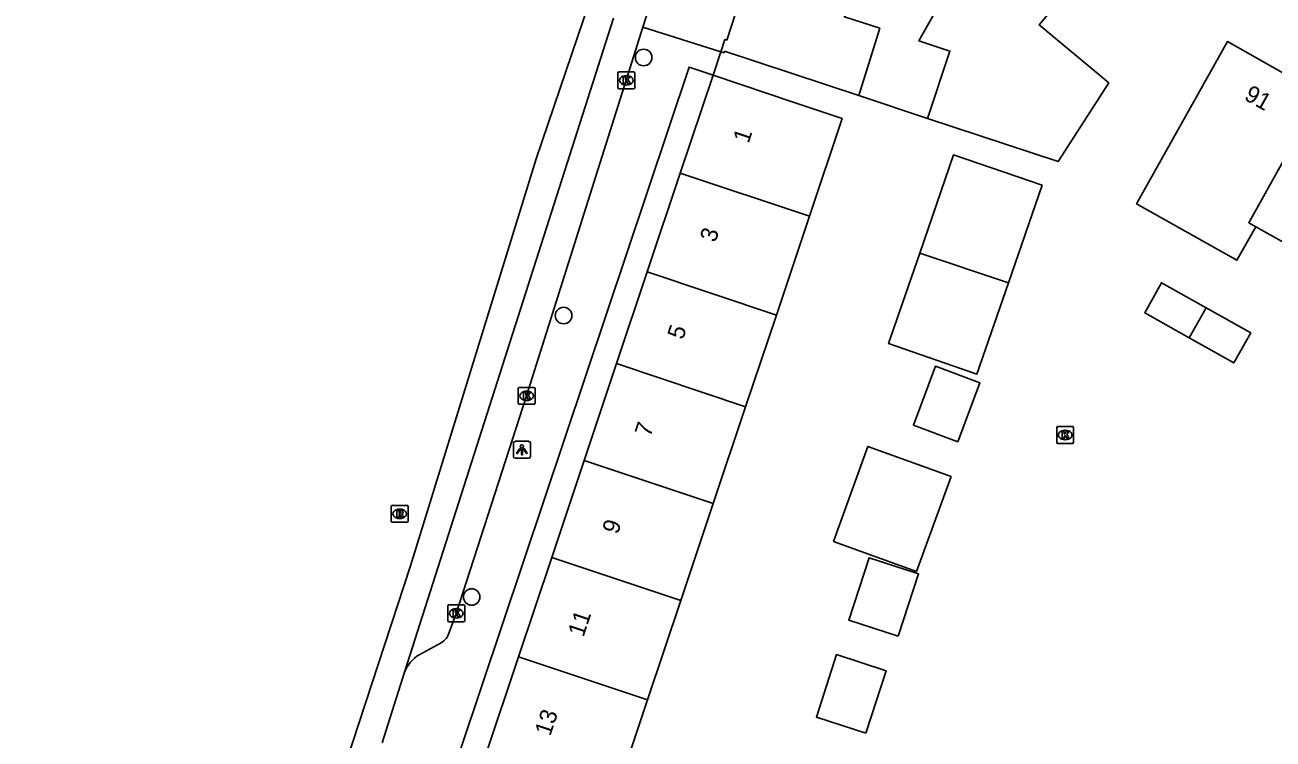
# Model space of a CAD drawing. Extents: x 163150 to 163546, y 380933 to 381635.
# Drawn here: x 163218.8 to 163292.5, y 381558 to 381600.2 of the extents above; entities that cross this region are included whole.
import ezdxf

# ---------------------------------------------------------------- set-up
doc = ezdxf.new("R2010")
doc.units = 0
for name, color, linetype in [('IMGEO_Boom', 7, 'Continuous'), ('IMGEO_Fietspad_gesloten', 7, 'Continuous'), ('IMGEO_Kolk', 7, 'Continuous'), ('IMGEO_Lichtpunt', 7, 'Continuous'), ('IMGEO_Pand', 7, 'Continuous'), ('IMGEO_Pand_nummerreeks', 7, 'Continuous'), ('IMGEO_Rijbaan_lokaal_gesloten', 7, 'Continuous'), ('IMGEO_Rioolput', 7, 'Continuous'), ('IMGEO_Voetpad_open', 7, 'Continuous')]:
    doc.layers.add(name, color=color, linetype=linetype)

msp = doc.modelspace()

# ---------------------------------------------------------------- linework, layer by layer
at = {"layer": 'IMGEO_Boom'}
for centre in [(163255.328, 381598.265), (163250.601, 381583.028), (163245.175, 381566.408)]:
    msp.add_circle(centre, 0.489, dxfattribs=at)
at = {"layer": 'IMGEO_Fietspad_gesloten'}
for points in [[(163253.553, 381600.588), (163241.214, 381561.974)], [(163241.214, 381561.974), (163239.892, 381557.795)]]:
    msp.add_lwpolyline(points, dxfattribs=at)
at = {"layer": 'IMGEO_Kolk'}
for p, q in [((163253.809, 381596.493), (163253.809, 381597.345)), ((163253.884, 381597.419), (163254.736, 381597.419)), ((163254.297, 381597.199), (163254.322, 381597.199)), ((163254.81, 381597.345), (163254.81, 381596.493)), ((163254.736, 381596.419), (163253.884, 381596.419)), ((163254.32, 381596.639), (163254.295, 381596.639)), ((163247.92, 381577.859), (163247.92, 381578.711)), ((163247.995, 381578.785), (163248.847, 381578.785)), ((163248.408, 381578.565), (163248.433, 381578.565)), ((163248.921, 381578.711), (163248.921, 381577.859)), ((163248.847, 381577.785), (163247.995, 381577.785)), ((163248.431, 381578.005), (163248.406, 381578.005)), ((163279.718, 381575.55), (163279.718, 381576.402)), ((163279.793, 381576.476), (163280.645, 381576.476)), ((163280.206, 381576.256), (163280.231, 381576.256)), ((163280.719, 381576.402), (163280.719, 381575.55)), ((163280.229, 381575.696), (163280.204, 381575.696)), ((163280.645, 381575.476), (163279.793, 381575.476)), ((163243.843, 381565.94), (163244.695, 381565.94)), ((163243.768, 381565.014), (163243.768, 381565.866)), ((163244.256, 381565.72), (163244.281, 381565.72)), ((163244.769, 381565.866), (163244.769, 381565.014)), ((163244.695, 381564.94), (163243.843, 381564.94)), ((163244.279, 381565.16), (163244.254, 381565.16))]:
    msp.add_line(p, q, dxfattribs=at)
for points in [[(163253.809, 381596.493), (163253.809, 381597.345)], [(163253.884, 381597.419), (163254.736, 381597.419)], [(163254.13, 381597.119), (163254.253, 381597.119), (163254.253, 381596.968), (163254.383, 381597.119), (163254.547, 381597.119), (163254.401, 381596.968), (163254.554, 381596.719), (163254.402, 381596.719), (163254.317, 381596.883), (163254.253, 381596.816), (163254.253, 381596.719), (163254.13, 381596.719), (163254.13, 381597.119)], [(163254.81, 381597.345), (163254.81, 381596.493)], [(163254.736, 381596.419), (163253.884, 381596.419)], [(163247.92, 381577.859), (163247.92, 381578.711)], [(163247.995, 381578.785), (163248.847, 381578.785)], [(163248.241, 381578.485), (163248.364, 381578.485), (163248.364, 381578.334), (163248.494, 381578.485), (163248.658, 381578.485), (163248.512, 381578.334), (163248.665, 381578.085), (163248.513, 381578.085), (163248.428, 381578.249), (163248.364, 381578.182), (163248.364, 381578.085), (163248.241, 381578.085), (163248.241, 381578.485)], [(163248.921, 381578.711), (163248.921, 381577.859)], [(163248.847, 381577.785), (163247.995, 381577.785)], [(163279.718, 381575.55), (163279.718, 381576.402)], [(163279.793, 381576.476), (163280.645, 381576.476)], [(163280.719, 381576.402), (163280.719, 381575.55)], [(163280.039, 381576.176), (163280.162, 381576.176), (163280.162, 381576.025), (163280.292, 381576.176), (163280.456, 381576.176), (163280.31, 381576.025), (163280.463, 381575.776), (163280.311, 381575.776), (163280.226, 381575.94), (163280.162, 381575.873), (163280.162, 381575.776), (163280.039, 381575.776), (163280.039, 381576.176)], [(163280.645, 381575.476), (163279.793, 381575.476)], [(163243.843, 381565.94), (163244.695, 381565.94)], [(163243.768, 381565.014), (163243.768, 381565.866)], [(163244.089, 381565.64), (163244.212, 381565.64), (163244.212, 381565.489), (163244.342, 381565.64), (163244.506, 381565.64), (163244.36, 381565.489), (163244.513, 381565.24), (163244.361, 381565.24), (163244.276, 381565.404), (163244.212, 381565.337), (163244.212, 381565.24), (163244.089, 381565.24), (163244.089, 381565.64)], [(163244.769, 381565.866), (163244.769, 381565.014)], [(163244.695, 381564.94), (163243.843, 381564.94)]]:
    msp.add_lwpolyline(points, dxfattribs=at)
for centre, start, end in [((163253.886, 381597.343), 91.55205, 178.44795), ((163253.886, 381597.343), 91.55205, 178.44795), ((163254.734, 381597.343), 1.55205, 88.44795), ((163254.734, 381597.343), 1.55205, 88.44795), ((163253.886, 381596.495), 181.55205, 268.44795), ((163253.886, 381596.495), 181.55205, 268.44795), ((163254.734, 381596.495), 271.55205, 358.44795), ((163254.734, 381596.495), 271.55205, 358.44795), ((163247.997, 381578.709), 91.55205, 178.44795), ((163247.997, 381578.709), 91.55205, 178.44795), ((163248.845, 381578.709), 1.55205, 88.44795), ((163248.845, 381578.709), 1.55205, 88.44795), ((163247.997, 381577.861), 181.55205, 268.44795), ((163247.997, 381577.861), 181.55205, 268.44795), ((163248.845, 381577.861), 271.55205, 358.44795), ((163248.845, 381577.861), 271.55205, 358.44795), ((163279.795, 381576.4), 91.55205, 178.44795), ((163279.795, 381576.4), 91.55205, 178.44795), ((163280.643, 381576.4), 1.55205, 88.44795), ((163280.643, 381576.4), 1.55205, 88.44795), ((163279.795, 381575.552), 181.55205, 268.44795), ((163279.795, 381575.552), 181.55205, 268.44795), ((163280.643, 381575.552), 271.55205, 358.44795), ((163280.643, 381575.552), 271.55205, 358.44795), ((163243.845, 381565.864), 91.55205, 178.44795), ((163243.845, 381565.864), 91.55205, 178.44795), ((163244.693, 381565.864), 1.55205, 88.44795), ((163244.693, 381565.864), 1.55205, 88.44795), ((163243.845, 381565.016), 181.55205, 268.44795), ((163243.845, 381565.016), 181.55205, 268.44795), ((163244.693, 381565.016), 271.55205, 358.44795), ((163244.693, 381565.016), 271.55205, 358.44795)]:
    msp.add_arc(centre, 0.0765, start, end, dxfattribs=at)
for centre, major_axis, ratio, start_param, end_param in [((163254.296, 381596.919), (-0.387, 0.002), 0.722429, 4.712389, 7.853982), ((163254.321, 381596.919), (-0.39, 0.002), 0.717154, 1.570796, 4.712389), ((163248.407, 381578.285), (-0.387, 0.002), 0.722429, 4.712389, 7.853982), ((163248.432, 381578.285), (-0.39, 0.002), 0.717154, 1.570796, 4.712389), ((163280.205, 381575.976), (-0.387, 0.002), 0.722429, 4.712389, 7.853982), ((163280.23, 381575.976), (-0.39, 0.002), 0.717154, 1.570796, 4.712389), ((163244.255, 381565.44), (-0.387, 0.002), 0.722429, 4.712389, 7.853982), ((163244.28, 381565.44), (-0.39, 0.002), 0.717154, 1.570796, 4.712389)]:
    msp.add_ellipse(centre, major_axis=major_axis, ratio=ratio, start_param=start_param, end_param=end_param, dxfattribs=at)
at = {"layer": 'IMGEO_Lichtpunt'}
for p, q in [((163248.546, 381575.6), (163247.738, 381575.6)), ((163248.546, 381575.6), (163247.738, 381575.6)), ((163247.644, 381575.505), (163247.644, 381574.698)), ((163247.644, 381575.505), (163247.644, 381574.698)), ((163248.64, 381574.698), (163248.64, 381575.505)), ((163248.64, 381574.698), (163248.64, 381575.505)), ((163247.738, 381574.604), (163248.546, 381574.604)), ((163247.738, 381574.604), (163248.546, 381574.604))]:
    msp.add_line(p, q, dxfattribs=at)
for points in [[(163248.018, 381575.169), (163248.057, 381575.141), (163247.869, 381574.879), (163247.831, 381574.906), (163248.018, 381575.169)], [(163248.12, 381575.121), (163248.167, 381575.121), (163248.167, 381574.799), (163248.12, 381574.799), (163248.12, 381575.121)], [(163248.23, 381575.141), (163248.268, 381575.168), (163248.455, 381574.906), (163248.416, 381574.878), (163248.23, 381575.141)]]:
    msp.add_lwpolyline(points, dxfattribs=at)
msp.add_circle((163248.143, 381575.303), 0.0994, dxfattribs=at)
for centre, start, end in [((163247.738, 381575.505), 90, 180), ((163247.738, 381575.505), 90, 180), ((163248.546, 381575.505), 0, 90), ((163248.546, 381575.505), 0, 90), ((163247.738, 381574.698), 180, 270), ((163247.738, 381574.698), 180, 270), ((163248.546, 381574.698), 270, 0), ((163248.546, 381574.698), 270, 360)]:
    msp.add_arc(centre, 0.0946, start, end, dxfattribs=at)
at = {"layer": 'IMGEO_Pand'}
for points in [[(163276.149, 381614.464), (163269.4, 381606.423), (163267.187, 381600.676), (163269.266, 381599.996), (163268.035, 381596.014)], [(163280.295, 381610.934), (163273.609, 381602.862), (163271.582, 381599.255), (163273.399, 381598.644), (163272.09, 381594.672)], [(163286.053, 381608.305), (163285.797, 381607.998), (163285.439, 381608.296), (163278.684, 381600.193), (163282.792, 381596.768), (163279.804, 381592.118), (163272.09, 381594.672)], [(163262.321, 381605.753), (163261.296, 381602.58), (163260.232, 381599.291), (163260.129, 381599.328), (163259.878, 381598.61)], [(163291.473, 381588.273), (163290.364, 381586.292), (163284.431, 381589.615), (163289.803, 381599.209), (163295.296, 381596.106)], [(163268.035, 381596.014), (163260.111, 381598.637), (163260.077, 381598.542), (163259.878, 381598.61)], [(163257.492, 381591.438), (163259.425, 381597.215)], [(163259.425, 381597.215), (163264.156, 381595.634), (163267.048, 381594.665), (163265.116, 381588.888)], [(163272.09, 381594.672), (163268.035, 381596.014)], [(163291.473, 381588.273), (163291.059, 381588.505), (163295.296, 381596.106)], [(163271.63, 381586.709), (163273.631, 381592.518), (163278.853, 381590.719), (163276.867, 381584.957)], [(163255.542, 381585.608), (163257.492, 381591.438)], [(163257.492, 381591.438), (163265.116, 381588.888)], [(163265.116, 381588.888), (163263.165, 381583.058)], [(163296.548, 381585.428), (163291.473, 381588.273)], [(163276.867, 381584.957), (163275.012, 381579.573), (163269.79, 381581.372), (163271.63, 381586.709)], [(163276.867, 381584.957), (163271.63, 381586.709)], [(163253.729, 381580.189), (163255.542, 381585.608)], [(163263.165, 381583.058), (163255.542, 381585.608)], [(163287.546, 381581.708), (163284.919, 381583.187), (163285.904, 381584.969), (163288.544, 381583.481)], [(163263.165, 381583.058), (163261.353, 381577.64)], [(163288.544, 381583.481), (163291.174, 381581.999), (163290.173, 381580.229), (163287.546, 381581.708)], [(163287.546, 381581.708), (163288.544, 381583.481)], [(163251.816, 381574.469), (163253.729, 381580.189)], [(163261.353, 381577.64), (163253.729, 381580.189)], [(163273.873, 381575.577), (163271.259, 381576.552), (163272.558, 381580.035), (163275.173, 381579.06), (163273.873, 381575.577)], [(163261.353, 381577.64), (163259.439, 381571.919)], [(163271.445, 381567.909), (163266.543, 381569.686), (163268.576, 381575.297), (163273.478, 381573.52), (163271.445, 381567.909)], [(163249.902, 381568.747), (163251.816, 381574.469)], [(163251.816, 381574.469), (163259.439, 381571.919)], [(163259.439, 381571.919), (163257.525, 381566.197)], [(163247.938, 381562.876), (163249.902, 381568.747)], [(163257.525, 381566.197), (163249.902, 381568.747)], [(163270.367, 381564.091), (163267.442, 381565.04), (163268.639, 381568.728), (163271.563, 381567.779), (163270.367, 381564.091)], [(163257.525, 381566.197), (163255.562, 381560.327)], [(163268.453, 381558.369), (163265.528, 381559.318), (163266.725, 381563.006), (163269.649, 381562.057), (163268.453, 381558.369)], [(163245.966, 381556.982), (163247.938, 381562.876)], [(163255.562, 381560.327), (163247.938, 381562.876)], [(163255.562, 381560.327), (163253.59, 381554.433)]]:
    msp.add_lwpolyline(points, dxfattribs=at)
at = {"layer": 'IMGEO_Rijbaan_lokaal_gesloten'}
msp.add_lwpolyline([(163166.425, 381280.691), (163188.546, 381358.485), (163194.244, 381378.759), (163197.853, 381391.449), (163199.503, 381397.64), (163199.813, 381399.806), (163200.997, 381406.978), (163202.361, 381414.066), (163203.421, 381419.565), (163203.421, 381421.474), (163203.421, 381430.45), (163203.421, 381436.022), (163203.704, 381437.827), (163206.489, 381449.486), (163214.12, 381481.676), (163216.801, 381492.716), (163218.451, 381497.565), (163223.711, 381513.764), (163241.568, 381568.239), (163248.986, 381592.289), (163253.519, 381605.619), (163255.545, 381608.986), (163259.826, 381616.311)], dxfattribs=at)
at = {"layer": 'IMGEO_Rioolput'}
for p, q in [((163240.427, 381570.894), (163240.427, 381571.746)), ((163240.502, 381571.82), (163241.354, 381571.82)), ((163240.915, 381571.6), (163240.94, 381571.6)), ((163241.428, 381571.746), (163241.428, 381570.894)), ((163241.354, 381570.82), (163240.502, 381570.82)), ((163240.938, 381571.04), (163240.913, 381571.04))]:
    msp.add_line(p, q, dxfattribs=at)
for points in [[(163240.427, 381570.894), (163240.427, 381571.746)], [(163240.502, 381571.82), (163241.354, 381571.82)], [(163241.016, 381571.518), (163240.764, 381571.52), (163240.764, 381571.12)], [(163240.764, 381571.12), (163240.888, 381571.12), (163240.888, 381571.282), (163240.899, 381571.282)], [(163240.942, 381571.439), (163240.888, 381571.439), (163240.888, 381571.358)], [(163240.888, 381571.358), (163240.94, 381571.358)], [(163240.946, 381571.253), (163241.017, 381571.12), (163241.157, 381571.12), (163241.092, 381571.246)], [(163241.428, 381571.746), (163241.428, 381570.894)], [(163241.354, 381570.82), (163240.502, 381570.82)]]:
    msp.add_lwpolyline(points, dxfattribs=at)
for centre, radius, start, end in [((163240.504, 381571.744), 0.0765, 91.55205, 178.44795), ((163240.504, 381571.744), 0.0765, 91.55205, 178.44795), ((163240.898, 381571.229), 0.0533, 26.02933, 88.69889), ((163240.924, 381571.547), 0.19, 274.7715, 282.96867), ((163240.948, 381571.343), 0.0964, 77.00612, 93.18647), ((163240.962, 381571.4), 0.0378, 276.66336, 79.67722), ((163241.015, 381571.408), 0.109, 350.36119, 89.41601), ((163241.013, 381571.408), 0.112, 277.58423, 350.98172), ((163240.997, 381571.193), 0.108, 29.51342, 73.79051), ((163241.352, 381571.744), 0.0765, 1.55205, 88.44795), ((163241.352, 381571.744), 0.0765, 1.55205, 88.44795), ((163240.504, 381570.896), 0.0765, 181.55205, 268.44795), ((163240.504, 381570.896), 0.0765, 181.55205, 268.44795), ((163241.352, 381570.896), 0.0765, 271.55205, 358.44795), ((163241.352, 381570.896), 0.0765, 271.55205, 358.44795)]:
    msp.add_arc(centre, radius, start, end, dxfattribs=at)
for centre, major_axis, ratio, start_param, end_param in [((163240.914, 381571.32), (-0.387, 0.002), 0.722429, 4.712389, 7.853982), ((163240.939, 381571.32), (-0.39, 0.002), 0.717154, 1.570796, 4.712389)]:
    msp.add_ellipse(centre, major_axis=major_axis, ratio=ratio, start_param=start_param, end_param=end_param, dxfattribs=at)
at = {"layer": 'IMGEO_Voetpad_open'}
for points in [[(163255.285, 381600.053), (163257.614, 381607.331)], [(163243.851, 381564.302), (163244.263, 381565.441), (163248.415, 381578.286), (163254.305, 381596.919), (163255.285, 381600.053)], [(163259.878, 381598.61), (163255.285, 381600.053)], [(163259.878, 381598.61), (163259.425, 381597.215)], [(163259.425, 381597.215), (163258.011, 381597.702), (163231.091, 381517.353), (163230.707, 381515.914)], [(163242.079, 381563.001), (163243.365, 381563.698)]]:
    msp.add_lwpolyline(points, dxfattribs=at)
for centre, radius, start, end in [((163242.821, 381564.633), 1.082, 300.17915, 342.17805), ((163243.122, 381561.245), 2.042, 120.7014, 159.08648)]:
    msp.add_arc(centre, radius, start, end, dxfattribs=at)

# ---------------------------------------------------------------- texts
at = {"layer": 'IMGEO_Pand_nummerreeks'}
for s, rotation, p in [('91', 330.53851, (163290.724, 381595.818)), ('1', 71.5035, (163261.524, 381593.15)), ('3', 71.5035, (163259.566, 381587.299)), ('5', 71.5035, (163257.645, 381581.556)), ('7', 71.5035, (163255.724, 381575.813)), ('9', 71.5035, (163253.803, 381570.07)), ('11', 71.5035, (163251.773, 381563.998)), ('13', 71.5035, (163249.814, 381558.147))]:
    msp.add_text(s, height=1, rotation=rotation, dxfattribs=at).set_placement(p)

doc.saveas('drawing.dxf')
